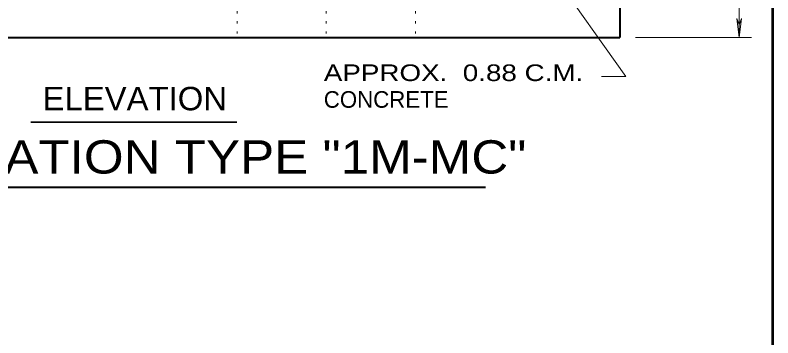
# Model space of a CAD drawing. Extents: x 312583 to 312854, y 144419 to 144597.
# Drawn here: x 312733.6 to 312768.24, y 144508.27 to 144523.01 of the extents above; entities that cross this region are included whole.
import ezdxf
from ezdxf.enums import TextEntityAlignment as Align

# ---------------------------------------------------------------- set-up
doc = ezdxf.new("R2010")
doc.units = 0
doc.header["$LTSCALE"] = 0.3
doc.linetypes.add('DOTTED', pattern=[1.5, 0.3, -1.2])
doc.layers.add('1', color=7, linetype='Continuous', lineweight=25)
doc.layers.add('2', color=7, linetype='Continuous', lineweight=13)

msp = doc.modelspace()

# ---------------------------------------------------------------- linework, layer by layer
at = {"layer": '1', "lineweight": 53}
msp.add_line((312768.237, 144506.4889), (312768.237, 144585.0846), dxfattribs=at)
at = {"layer": '1', "lineweight": 40}
for p in [(312761.2385, 144544.3469), (312721.6325, 144521.9833)]:
    msp.add_line(p, (312761.2385, 144521.9833), dxfattribs=at)
at = {"layer": '2'}
for p, q in [((312766.6945, 144521.9833), (312766.6945, 144544.9833)), ((312766.5872, 144522.8496), (312766.6945, 144522.5736)), ((312766.6945, 144521.9833), (312766.5872, 144522.8496)), ((312766.8019, 144522.8496), (312766.6945, 144522.5736)), ((312766.6945, 144521.9833), (312766.8019, 144522.8496)), ((312761.9591, 144521.9833), (312767.2539, 144521.9833))]:
    msp.add_line(p, q, dxfattribs=at)
at = {"layer": '2', "linetype": 'DOTTED'}
for p, q in [((312743.7508, 144523.6469), (312743.7508, 144522.0293)), ((312747.8218, 144523.6469), (312747.8218, 144521.9909)), ((312751.9005, 144523.6469), (312751.9005, 144522.0676))]:
    msp.add_line(p, q, dxfattribs=at)
at = {"layer": '2', "lineweight": 35}
msp.add_line((312734.3144, 144518.123), (312743.729, 144518.123), dxfattribs=at)
at = {"layer": '2', "lineweight": 40}
msp.add_line((312724.8831, 144515.1523), (312755.0975, 144515.1523), dxfattribs=at)
at = {"layer": '2'}
msp.add_lwpolyline([(312760.4028, 144520.2046), (312761.5145, 144520.2046), (312758.1795, 144524.9043)], dxfattribs=at)

# ---------------------------------------------------------------- texts
at = {"layer": '2', "width": 1.25}
msp.add_text('APPROX.  0.88 C.M.', height=0.76, dxfattribs=at).set_placement((312747.7084, 144519.9976))
at = {"layer": '2'}
for s, height, width, p in [('ELEVATION', 1.07, 1.05, (312739.0685, 144518.6636)), ('FOUNDATION TYPE "1M-MC"', 1.52, 1.15, (312740.8817, 144515.7733))]:
    msp.add_text(s, height=height, dxfattribs=dict(at, width=width)).set_placement(p, align=Align.CENTER)
msp.add_text('CONCRETE', height=0.76, dxfattribs=at).set_placement((312747.7084, 144518.7776))

doc.saveas('drawing.dxf')
